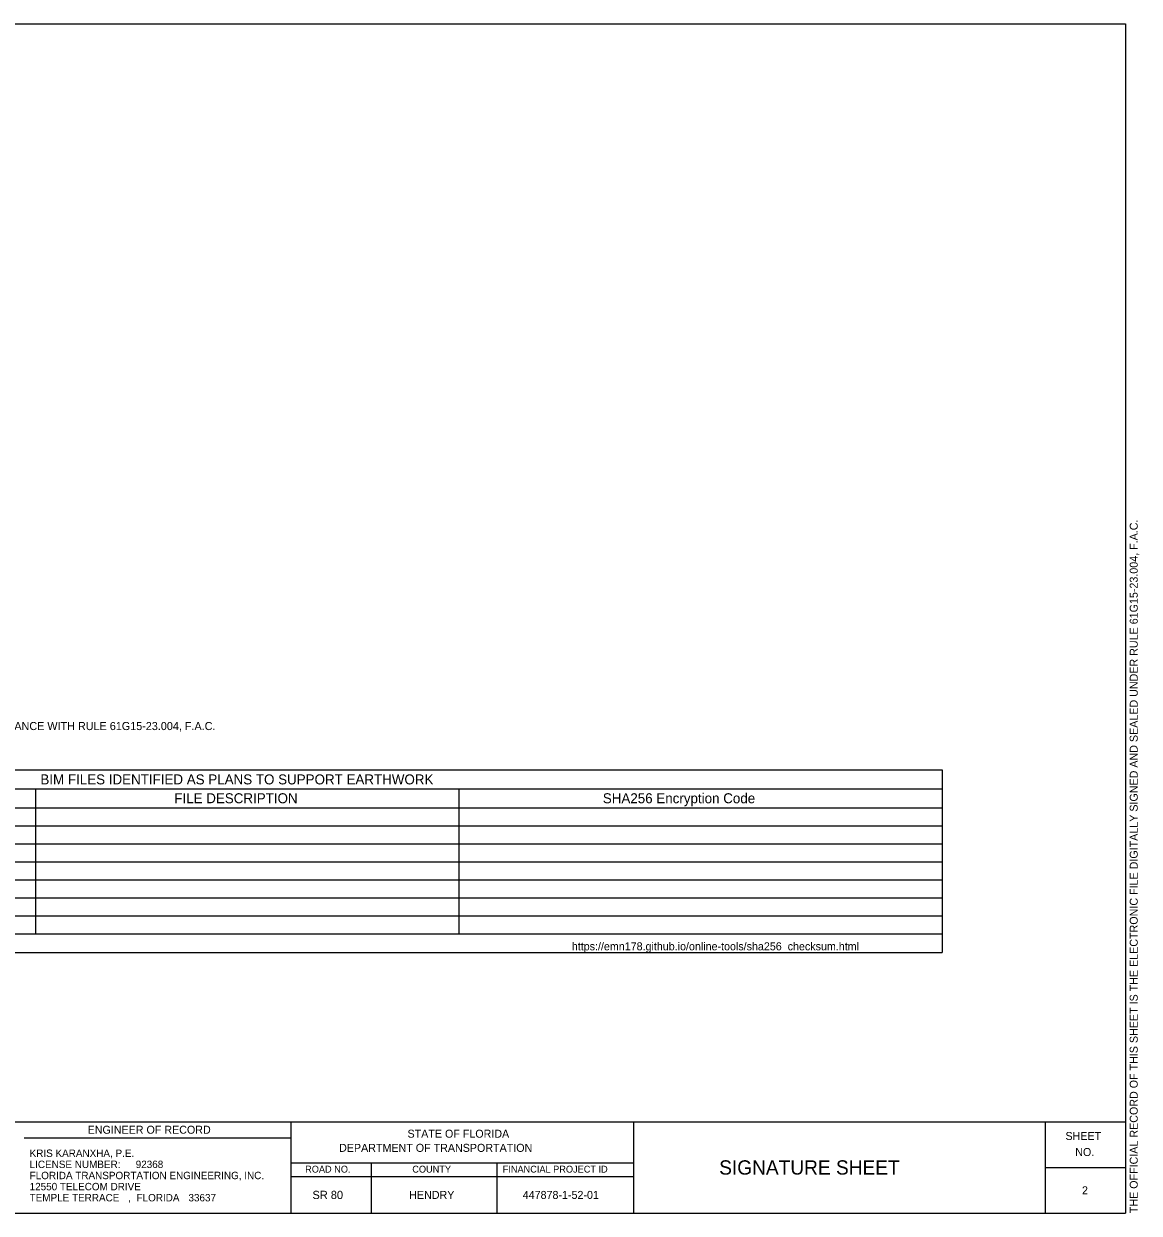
# Model space of a CAD drawing. Extents: x 0.03 to 1.34, y 0 to 0.87.
# Drawn here: x 0.526 to 1.339, y 0.004 to 0.871 of the extents above; entities that cross this region are included whole.
import ezdxf

# ---------------------------------------------------------------- set-up
doc = ezdxf.new("R2010")
doc.units = 0
for name, color, linetype in [('SheetBorder_dp', 7, 'Continuous'), ('SheetLines_dp', 7, 'Continuous'), ('SumBoxBorder_dp', 7, 'Continuous'), ('SumBoxLines_dp', 7, 'Continuous'), ('SumBoxLinesMin_dp', 7, 'Continuous'), ('TextLabel', 7, 'Continuous'), ('TextMisc', 7, 'Continuous'), ('TextNotes', 7, 'Continuous'), ('TextShtNo', 7, 'Continuous')]:
    doc.layers.add(name, color=color, linetype=linetype)

msp = doc.modelspace()

# ---------------------------------------------------------------- linework, layer by layer
at = {"layer": 'SheetBorder_dp'}
for p, q in [((0.04583, 0.87083), (1.32916, 0.87083)), ((1.32916, 0.87083), (1.32916, 0.00417)), ((0.04583, 0.07083), (1.32916, 0.07083)), ((0.04583, 0.00417), (1.32916, 0.00417))]:
    msp.add_line(p, q, dxfattribs=at)
at = {"layer": 'SheetLines_dp'}
for p, q in [((0.72083, 0.07083), (0.72083, 0.00417)), ((0.97083, 0.00417), (0.97083, 0.07083)), ((1.27083, 0.00417), (1.27083, 0.07083)), ((0.52621, 0.05917), (0.72084, 0.05917)), ((0.72083, 0.04083), (0.97083, 0.04083)), ((0.77916, 0.04083), (0.77916, 0.00417)), ((0.87083, 0.04083), (0.87083, 0.00417)), ((1.27083, 0.0375), (1.32916, 0.0375)), ((0.72083, 0.03083), (0.97083, 0.03083))]:
    msp.add_line(p, q, dxfattribs=at)
at = {"layer": 'SumBoxBorder_dp'}
for p, q in [((0.22585, 0.32714), (1.19547, 0.32714)), ((1.19547, 0.32714), (1.19547, 0.19407)), ((0.22585, 0.19407), (1.19547, 0.19407))]:
    msp.add_line(p, q, dxfattribs=at)
at = {"layer": 'SumBoxLines_dp'}
for p, q in [((0.22585, 0.31339), (1.19547, 0.31339)), ((0.22585, 0.31339), (1.19547, 0.31339)), ((0.22585, 0.20781), (1.19547, 0.20781))]:
    msp.add_line(p, q, dxfattribs=at)
at = {"layer": 'SumBoxLinesMin_dp'}
for p, q in [((0.53448, 0.31339), (0.53448, 0.20781)), ((0.53448, 0.31339), (0.53448, 0.20781)), ((0.84311, 0.31339), (0.84311, 0.20781)), ((0.84311, 0.31339), (0.84311, 0.20781)), ((0.22585, 0.29965), (1.19547, 0.29965)), ((0.22585, 0.29965), (1.19547, 0.29965)), ((0.22585, 0.28653), (1.19547, 0.28653)), ((0.22585, 0.28653), (1.19547, 0.28653)), ((0.22585, 0.27341), (1.19547, 0.27341)), ((0.22585, 0.27341), (1.19547, 0.27341)), ((0.22585, 0.26029), (1.19547, 0.26029)), ((0.22585, 0.26029), (1.19547, 0.26029)), ((0.22585, 0.24717), (1.19547, 0.24717)), ((0.22585, 0.24717), (1.19547, 0.24717)), ((0.22585, 0.23405), (1.19547, 0.23405)), ((0.22585, 0.23405), (1.19547, 0.23405)), ((0.22585, 0.22093), (1.19547, 0.22093)), ((0.22585, 0.22093), (1.19547, 0.22093))]:
    msp.add_line(p, q, dxfattribs=at)

# ---------------------------------------------------------------- texts
at = {"layer": 'TextLabel'}
for s, height, p in [('BIM FILES IDENTIFIED AS PLANS TO SUPPORT EARTHWORK', 0.0072888, (0.53816, 0.31662)), ('FILE DESCRIPTION', 0.0072888, (0.63575, 0.30288)), ('SHA256 Encryption Code', 0.0072888, (0.94816, 0.30288)), ('https://emn178.github.io/online-tools/sha256_checksum.html', 0.005831, (0.92556, 0.19573))]:
    msp.add_text(s, height=height, dxfattribs=at).set_placement(p)
at = {"layer": 'TextMisc'}
for s, height, rotation, p in [('THE OFFICIAL RECORD OF THIS SHEET IS THE ELECTRONIC FILE DIGITALLY SIGNED AND SEALED UNDER RULE 61G15-23.004, F.A.C.', 0.00583333, 90, (1.33811, 0.00419)), ('SHEET', 0.005833, 359.86066, (1.2854, 0.05754)), ('NO.', 0.005833, 359.86066, (1.29254, 0.04586))]:
    msp.add_text(s, height=height, rotation=rotation, dxfattribs=at).set_placement(p)
for s, height, p in [('ENGINEER OF RECORD', 0.0058333, (0.57258, 0.06208)), ('STATE OF FLORIDA', 0.0058333, (0.80578, 0.05918)), ('DEPARTMENT OF TRANSPORTATION', 0.0058333, (0.75589, 0.04888)), ('KRIS KARANXHA, P.E.', 0.0054, (0.5303, 0.04517)), ('LICENSE NUMBER: ', 0.0054, (0.5303, 0.03707)), ('92368', 0.0054, (0.60762, 0.03707)), ('ROAD NO.', 0.005, (0.73115, 0.03376)), ('COUNTY', 0.005, (0.80925, 0.03376)), ('FINANCIAL PROJECT ID', 0.005, (0.87518, 0.03376)), ('SIGNATURE SHEET', 0.0104166, (1.03299, 0.03229)), ('12550 TELECOM DRIVE', 0.0054, (0.5303, 0.02087)), ('FLORIDA TRANSPORTATION ENGINEERING, INC.', 0.0054, (0.5303, 0.02897)), ('TEMPLE TERRACE', 0.0054, (0.5303, 0.01277)), ('FLORIDA', 0.0054, (0.60824, 0.01277)), ('33637', 0.0054, (0.64608, 0.01277)), ('SR 80', 0.006, (0.73648, 0.0145)), ('HENDRY', 0.005833, (0.80701, 0.01458)), ('447878-1-52-01', 0.0058331, (0.88977, 0.01458)), (', ', 0.0054, (0.60209, 0.01277))]:
    msp.add_text(s, height=height, dxfattribs=at).set_placement(p)
at = {"layer": 'TextNotes'}
msp.add_text('THE ABOVE NAMED PROFESSIONAL IS RESPONSIBLE FOR THE FOLLOWING BIM FILES IN ACCORDANCE WITH RULE 61G15-23.004, F.A.C.', height=0.0058899, dxfattribs=at).set_placement((0.13971, 0.3562))
at = {"layer": 'TextShtNo'}
msp.add_text('2', height=0.00583, dxfattribs=at).set_placement((1.29747, 0.01792))

doc.saveas('drawing.dxf')
